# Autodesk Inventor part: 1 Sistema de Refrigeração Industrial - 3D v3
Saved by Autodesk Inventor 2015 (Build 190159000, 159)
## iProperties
Created: 2015-06
Part Number: 1 Sistema de Refrigeração Industrial - 3D v3
Material: Generic
Document SubType Name: Modeling
Designer: Franzi-CAD
Density: 1 g/cm^3
Appearance: 84,84,84_1
Translation Standard: IGES 5.3
FileName: 1 Sistema de RefrigeraÃ§Ã£o Industrial - 3D v3
PreProcessor: AutoCAD 2015 - English
PostProcessor: Build: 160, Release: 2012 RTM - Date: Tue 03/01/2011
Sent Units: millimeter
Uncertainty: 0.01
Author: Franzi-CAD
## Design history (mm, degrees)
node "1 Sistema de Refrigeração Industrial - 3D v3.iges1"
  sketch "3D Sketch1"
sketch "3D Sketch2"
node "1 Sistema de Refrigeração Industrial - 3D v3"
node "1 Sistema de Refrigeração Industrial - 3D v3_1"
node "1 Sistema de Refrigeração Industrial - 3D v3_2"
node "1 Sistema de Refrigeração Industrial - 3D v3_3"
node "1 Sistema de Refrigeração Industrial - 3D v3_4"
node "1 Sistema de Refrigeração Industrial - 3D v3_5"
node "1 Sistema de Refrigeração Industrial - 3D v3_6"
node "1 Sistema de Refrigeração Industrial - 3D v3_7"
node "1 Sistema de Refrigeração Industrial - 3D v3_8"
node "1 Sistema de Refrigeração Industrial - 3D v3_9"
node "1 Sistema de Refrigeração Industrial - 3D v3_10"
node "1 Sistema de Refrigeração Industrial - 3D v3_11"
node "1 Sistema de Refrigeração Industrial - 3D v3_12"
node "1 Sistema de Refrigeração Industrial - 3D v3_13"
node "1 Sistema de Refrigeração Industrial - 3D v3_14"
node "1 Sistema de Refrigeração Industrial - 3D v3_15"
node "1 Sistema de Refrigeração Industrial - 3D v3_16"
node "1 Sistema de Refrigeração Industrial - 3D v3_17"
node "1 Sistema de Refrigeração Industrial - 3D v3_18"
node "1 Sistema de Refrigeração Industrial - 3D v3_19"
node "1 Sistema de Refrigeração Industrial - 3D v3_20"
node "1 Sistema de Refrigeração Industrial - 3D v3_21"
node "1 Sistema de Refrigeração Industrial - 3D v3_22"
node "1 Sistema de Refrigeração Industrial - 3D v3_23"
node "1 Sistema de Refrigeração Industrial - 3D v3_24"
node "1 Sistema de Refrigeração Industrial - 3D v3_25"
node "1 Sistema de Refrigeração Industrial - 3D v3_26"
node "1 Sistema de Refrigeração Industrial - 3D v3_27"
node "1 Sistema de Refrigeração Industrial - 3D v3_28"
node "1 Sistema de Refrigeração Industrial - 3D v3_29"
node "1 Sistema de Refrigeração Industrial - 3D v3_30"
node "1 Sistema de Refrigeração Industrial - 3D v3_31"
node "1 Sistema de Refrigeração Industrial - 3D v3_32"
node "1 Sistema de Refrigeração Industrial - 3D v3_33"
node "1 Sistema de Refrigeração Industrial - 3D v3_34"
node "1 Sistema de Refrigeração Industrial - 3D v3_35"
node "1 Sistema de Refrigeração Industrial - 3D v3_36"
node "1 Sistema de Refrigeração Industrial - 3D v3_37"
node "1 Sistema de Refrigeração Industrial - 3D v3_38"
node "1 Sistema de Refrigeração Industrial - 3D v3_39"
node "1 Sistema de Refrigeração Industrial - 3D v3_40"
node "1 Sistema de Refrigeração Industrial - 3D v3_41"
node "1 Sistema de Refrigeração Industrial - 3D v3_42"
node "1 Sistema de Refrigeração Industrial - 3D v3_43"
node "1 Sistema de Refrigeração Industrial - 3D v3_44"
node "1 Sistema de Refrigeração Industrial - 3D v3_45"
node "1 Sistema de Refrigeração Industrial - 3D v3_46"
node "1 Sistema de Refrigeração Industrial - 3D v3_47"
node "1 Sistema de Refrigeração Industrial - 3D v3_48"
node "1 Sistema de Refrigeração Industrial - 3D v3_49"
node "1 Sistema de Refrigeração Industrial - 3D v3_50"
node "1 Sistema de Refrigeração Industrial - 3D v3_51"
node "1 Sistema de Refrigeração Industrial - 3D v3_52"
node "1 Sistema de Refrigeração Industrial - 3D v3_53"
node "1 Sistema de Refrigeração Industrial - 3D v3_54"
node "1 Sistema de Refrigeração Industrial - 3D v3_55"
node "1 Sistema de Refrigeração Industrial - 3D v3_56"
node "1 Sistema de Refrigeração Industrial - 3D v3_57"
node "1 Sistema de Refrigeração Industrial - 3D v3_58"
node "1 Sistema de Refrigeração Industrial - 3D v3_59"
node "1 Sistema de Refrigeração Industrial - 3D v3_60"
node "1 Sistema de Refrigeração Industrial - 3D v3_61"
node "1 Sistema de Refrigeração Industrial - 3D v3_62"
node "1 Sistema de Refrigeração Industrial - 3D v3_63"
node "1 Sistema de Refrigeração Industrial - 3D v3_64"
node "1 Sistema de Refrigeração Industrial - 3D v3_65"
node "1 Sistema de Refrigeração Industrial - 3D v3_66"
node "1 Sistema de Refrigeração Industrial - 3D v3_67"
node "1 Sistema de Refrigeração Industrial - 3D v3_68"
node "1 Sistema de Refrigeração Industrial - 3D v3_69"
node "1 Sistema de Refrigeração Industrial - 3D v3_70"
node "1 Sistema de Refrigeração Industrial - 3D v3_71"
node "1 Sistema de Refrigeração Industrial - 3D v3_72"
node "1 Sistema de Refrigeração Industrial - 3D v3_73"
node "1 Sistema de Refrigeração Industrial - 3D v3_74"
node "1 Sistema de Refrigeração Industrial - 3D v3_75"
node "1 Sistema de Refrigeração Industrial - 3D v3_76"
node "1 Sistema de Refrigeração Industrial - 3D v3_77"
node "1 Sistema de Refrigeração Industrial - 3D v3_78"
node "1 Sistema de Refrigeração Industrial - 3D v3_79"
node "1 Sistema de Refrigeração Industrial - 3D v3_80"
node "1 Sistema de Refrigeração Industrial - 3D v3_81"
node "1 Sistema de Refrigeração Industrial - 3D v3_82"
node "1 Sistema de Refrigeração Industrial - 3D v3_83"
node "1 Sistema de Refrigeração Industrial - 3D v3_84"
node "1 Sistema de Refrigeração Industrial - 3D v3_85"
node "1 Sistema de Refrigeração Industrial - 3D v3_86"
node "1 Sistema de Refrigeração Industrial - 3D v3_87"
node "1 Sistema de Refrigeração Industrial - 3D v3_88"
node "1 Sistema de Refrigeração Industrial - 3D v3_89"
node "1 Sistema de Refrigeração Industrial - 3D v3_90"
node "1 Sistema de Refrigeração Industrial - 3D v3_91"
node "1 Sistema de Refrigeração Industrial - 3D v3_92"
node "1 Sistema de Refrigeração Industrial - 3D v3_93"
node "1 Sistema de Refrigeração Industrial - 3D v3_94"
node "1 Sistema de Refrigeração Industrial - 3D v3_95"
node "1 Sistema de Refrigeração Industrial - 3D v3_96"
node "1 Sistema de Refrigeração Industrial - 3D v3_97"
node "1 Sistema de Refrigeração Industrial - 3D v3_98"
node "1 Sistema de Refrigeração Industrial - 3D v3_99"
node "1 Sistema de Refrigeração Industrial - 3D v3_100"
node "1 Sistema de Refrigeração Industrial - 3D v3_101"
node "1 Sistema de Refrigeração Industrial - 3D v3_102"
node "1 Sistema de Refrigeração Industrial - 3D v3_103"
node "1 Sistema de Refrigeração Industrial - 3D v3_104"
node "1 Sistema de Refrigeração Industrial - 3D v3_105"
node "1 Sistema de Refrigeração Industrial - 3D v3_106"
node "1 Sistema de Refrigeração Industrial - 3D v3_107"
node "1 Sistema de Refrigeração Industrial - 3D v3_108"
node "1 Sistema de Refrigeração Industrial - 3D v3_109"
node "1 Sistema de Refrigeração Industrial - 3D v3_110"
node "1 Sistema de Refrigeração Industrial - 3D v3_111"
node "1 Sistema de Refrigeração Industrial - 3D v3_112"
node "1 Sistema de Refrigeração Industrial - 3D v3_113"
node "1 Sistema de Refrigeração Industrial - 3D v3_114"
node "1 Sistema de Refrigeração Industrial - 3D v3_115"
node "1 Sistema de Refrigeração Industrial - 3D v3_116"
node "1 Sistema de Refrigeração Industrial - 3D v3_117"
node "1 Sistema de Refrigeração Industrial - 3D v3_118"
node "1 Sistema de Refrigeração Industrial - 3D v3_119"
node "1 Sistema de Refrigeração Industrial - 3D v3_120"
node "1 Sistema de Refrigeração Industrial - 3D v3_121"
node "1 Sistema de Refrigeração Industrial - 3D v3_122"
node "1 Sistema de Refrigeração Industrial - 3D v3_123"
node "1 Sistema de Refrigeração Industrial - 3D v3_124"
node "1 Sistema de Refrigeração Industrial - 3D v3_125"
node "1 Sistema de Refrigeração Industrial - 3D v3_126"
node "1 Sistema de Refrigeração Industrial - 3D v3_127"
node "1 Sistema de Refrigeração Industrial - 3D v3_128"
node "1 Sistema de Refrigeração Industrial - 3D v3_129"
node "1 Sistema de Refrigeração Industrial - 3D v3_130"
node "1 Sistema de Refrigeração Industrial - 3D v3_131"
node "1 Sistema de Refrigeração Industrial - 3D v3_132"
node "1 Sistema de Refrigeração Industrial - 3D v3_133"
node "1 Sistema de Refrigeração Industrial - 3D v3_134"
node "1 Sistema de Refrigeração Industrial - 3D v3_135"
node "1 Sistema de Refrigeração Industrial - 3D v3_136"
node "1 Sistema de Refrigeração Industrial - 3D v3_137"
node "1 Sistema de Refrigeração Industrial - 3D v3_138"
node "1 Sistema de Refrigeração Industrial - 3D v3_139"
node "1 Sistema de Refrigeração Industrial - 3D v3_140"
node "1 Sistema de Refrigeração Industrial - 3D v3_141"
node "1 Sistema de Refrigeração Industrial - 3D v3_142"
node "1 Sistema de Refrigeração Industrial - 3D v3_143"
node "1 Sistema de Refrigeração Industrial - 3D v3_144"
node "1 Sistema de Refrigeração Industrial - 3D v3_145"
node "1 Sistema de Refrigeração Industrial - 3D v3_146"
node "1 Sistema de Refrigeração Industrial - 3D v3_147"
node "1 Sistema de Refrigeração Industrial - 3D v3_148"
node "1 Sistema de Refrigeração Industrial - 3D v3_149"
node "1 Sistema de Refrigeração Industrial - 3D v3_150"
node "1 Sistema de Refrigeração Industrial - 3D v3_151"
node "1 Sistema de Refrigeração Industrial - 3D v3_152"
node "1 Sistema de Refrigeração Industrial - 3D v3_153"
node "1 Sistema de Refrigeração Industrial - 3D v3_154"
node "1 Sistema de Refrigeração Industrial - 3D v3_155"
node "1 Sistema de Refrigeração Industrial - 3D v3_156"
node "1 Sistema de Refrigeração Industrial - 3D v3_157"
node "1 Sistema de Refrigeração Industrial - 3D v3_158"
node "1 Sistema de Refrigeração Industrial - 3D v3_159"
node "1 Sistema de Refrigeração Industrial - 3D v3_160"
node "1 Sistema de Refrigeração Industrial - 3D v3_161"
node "1 Sistema de Refrigeração Industrial - 3D v3_162"
node "1 Sistema de Refrigeração Industrial - 3D v3_163"
node "1 Sistema de Refrigeração Industrial - 3D v3_164"
node "1 Sistema de Refrigeração Industrial - 3D v3_165"
node "1 Sistema de Refrigeração Industrial - 3D v3_166"
node "1 Sistema de Refrigeração Industrial - 3D v3_167"
node "1 Sistema de Refrigeração Industrial - 3D v3_168"
node "1 Sistema de Refrigeração Industrial - 3D v3_169"
node "1 Sistema de Refrigeração Industrial - 3D v3_170"
node "1 Sistema de Refrigeração Industrial - 3D v3_171"
node "1 Sistema de Refrigeração Industrial - 3D v3_172"
node "1 Sistema de Refrigeração Industrial - 3D v3_173"
node "1 Sistema de Refrigeração Industrial - 3D v3_174"
node "1 Sistema de Refrigeração Industrial - 3D v3_175"
node "1 Sistema de Refrigeração Industrial - 3D v3_176"
node "1 Sistema de Refrigeração Industrial - 3D v3_177"
node "1 Sistema de Refrigeração Industrial - 3D v3_178"
node "1 Sistema de Refrigeração Industrial - 3D v3_179"
node "1 Sistema de Refrigeração Industrial - 3D v3_180"
node "1 Sistema de Refrigeração Industrial - 3D v3_181"
node "1 Sistema de Refrigeração Industrial - 3D v3_182"
node "1 Sistema de Refrigeração Industrial - 3D v3_183"
node "1 Sistema de Refrigeração Industrial - 3D v3_184"
node "1 Sistema de Refrigeração Industrial - 3D v3_185"
node "1 Sistema de Refrigeração Industrial - 3D v3_186"
node "1 Sistema de Refrigeração Industrial - 3D v3_187"
node "1 Sistema de Refrigeração Industrial - 3D v3_188"
node "1 Sistema de Refrigeração Industrial - 3D v3_189"
node "1 Sistema de Refrigeração Industrial - 3D v3_190"
node "1 Sistema de Refrigeração Industrial - 3D v3_191"
node "1 Sistema de Refrigeração Industrial - 3D v3_192"
node "1 Sistema de Refrigeração Industrial - 3D v3_193"
node "1 Sistema de Refrigeração Industrial - 3D v3_194"
node "1 Sistema de Refrigeração Industrial - 3D v3_195"
node "1 Sistema de Refrigeração Industrial - 3D v3_196"
node "1 Sistema de Refrigeração Industrial - 3D v3_197"
node "1 Sistema de Refrigeração Industrial - 3D v3_198"
node "1 Sistema de Refrigeração Industrial - 3D v3_199"
node "1 Sistema de Refrigeração Industrial - 3D v3_200"
node "1 Sistema de Refrigeração Industrial - 3D v3_201"
node "1 Sistema de Refrigeração Industrial - 3D v3_202"
node "1 Sistema de Refrigeração Industrial - 3D v3_203"
node "1 Sistema de Refrigeração Industrial - 3D v3_204"
node "1 Sistema de Refrigeração Industrial - 3D v3_205"
node "1 Sistema de Refrigeração Industrial - 3D v3_206"
node "1 Sistema de Refrigeração Industrial - 3D v3_207"
node "1 Sistema de Refrigeração Industrial - 3D v3_208"
node "1 Sistema de Refrigeração Industrial - 3D v3_209"
node "1 Sistema de Refrigeração Industrial - 3D v3_210"
node "1 Sistema de Refrigeração Industrial - 3D v3_211"
node "1 Sistema de Refrigeração Industrial - 3D v3_212"
node "1 Sistema de Refrigeração Industrial - 3D v3_213"
node "1 Sistema de Refrigeração Industrial - 3D v3_214"
node "1 Sistema de Refrigeração Industrial - 3D v3_215"
node "1 Sistema de Refrigeração Industrial - 3D v3_216"
node "1 Sistema de Refrigeração Industrial - 3D v3_217"
node "1 Sistema de Refrigeração Industrial - 3D v3_218"
node "1 Sistema de Refrigeração Industrial - 3D v3_219"
node "1 Sistema de Refrigeração Industrial - 3D v3_220"
node "1 Sistema de Refrigeração Industrial - 3D v3_221"
node "1 Sistema de Refrigeração Industrial - 3D v3_222"
node "1 Sistema de Refrigeração Industrial - 3D v3_223"
node "1 Sistema de Refrigeração Industrial - 3D v3_224"
node "1 Sistema de Refrigeração Industrial - 3D v3_225"
node "1 Sistema de Refrigeração Industrial - 3D v3_226"
node "1 Sistema de Refrigeração Industrial - 3D v3_227"
node "1 Sistema de Refrigeração Industrial - 3D v3_228"
node "1 Sistema de Refrigeração Industrial - 3D v3_229"
node "1 Sistema de Refrigeração Industrial - 3D v3_230"
node "1 Sistema de Refrigeração Industrial - 3D v3_231"
node "1 Sistema de Refrigeração Industrial - 3D v3_232"
node "1 Sistema de Refrigeração Industrial - 3D v3_233"
node "1 Sistema de Refrigeração Industrial - 3D v3_234"
node "1 Sistema de Refrigeração Industrial - 3D v3_235"
node "1 Sistema de Refrigeração Industrial - 3D v3_236"
node "1 Sistema de Refrigeração Industrial - 3D v3_237"
node "1 Sistema de Refrigeração Industrial - 3D v3_238"
node "1 Sistema de Refrigeração Industrial - 3D v3_239"
node "1 Sistema de Refrigeração Industrial - 3D v3_240"
node "1 Sistema de Refrigeração Industrial - 3D v3_241"
node "1 Sistema de Refrigeração Industrial - 3D v3_242"
node "1 Sistema de Refrigeração Industrial - 3D v3_243"
node "1 Sistema de Refrigeração Industrial - 3D v3_244"
node "1 Sistema de Refrigeração Industrial - 3D v3_245"
node "1 Sistema de Refrigeração Industrial - 3D v3_246"
node "1 Sistema de Refrigeração Industrial - 3D v3_247"
node "1 Sistema de Refrigeração Industrial - 3D v3_248"
node "1 Sistema de Refrigeração Industrial - 3D v3_249"
node "1 Sistema de Refrigeração Industrial - 3D v3_250"
node "1 Sistema de Refrigeração Industrial - 3D v3_251"
node "1 Sistema de Refrigeração Industrial - 3D v3_252"
node "1 Sistema de Refrigeração Industrial - 3D v3_253"
node "1 Sistema de Refrigeração Industrial - 3D v3_254"
node "1 Sistema de Refrigeração Industrial - 3D v3_255"
node "1 Sistema de Refrigeração Industrial - 3D v3_256"
node "1 Sistema de Refrigeração Industrial - 3D v3_257"
node "1 Sistema de Refrigeração Industrial - 3D v3_258"
node "1 Sistema de Refrigeração Industrial - 3D v3_259"
node "1 Sistema de Refrigeração Industrial - 3D v3_260"
node "1 Sistema de Refrigeração Industrial - 3D v3_261"
node "1 Sistema de Refrigeração Industrial - 3D v3_262"
node "1 Sistema de Refrigeração Industrial - 3D v3_263"
node "1 Sistema de Refrigeração Industrial - 3D v3_264"
node "1 Sistema de Refrigeração Industrial - 3D v3_265"
node "1 Sistema de Refrigeração Industrial - 3D v3_266"
node "1 Sistema de Refrigeração Industrial - 3D v3_267"
node "1 Sistema de Refrigeração Industrial - 3D v3_268"
node "1 Sistema de Refrigeração Industrial - 3D v3_269"
node "1 Sistema de Refrigeração Industrial - 3D v3_270"
node "1 Sistema de Refrigeração Industrial - 3D v3_271"
node "1 Sistema de Refrigeração Industrial - 3D v3_272"
node "1 Sistema de Refrigeração Industrial - 3D v3_273"
node "1 Sistema de Refrigeração Industrial - 3D v3_274"
node "1 Sistema de Refrigeração Industrial - 3D v3_275"
node "1 Sistema de Refrigeração Industrial - 3D v3_276"
node "1 Sistema de Refrigeração Industrial - 3D v3_277"
node "1 Sistema de Refrigeração Industrial - 3D v3_278"
node "1 Sistema de Refrigeração Industrial - 3D v3_279"
node "1 Sistema de Refrigeração Industrial - 3D v3_280"
node "1 Sistema de Refrigeração Industrial - 3D v3_281"
node "1 Sistema de Refrigeração Industrial - 3D v3_282"
node "1 Sistema de Refrigeração Industrial - 3D v3_283"
node "1 Sistema de Refrigeração Industrial - 3D v3_284"
node "1 Sistema de Refrigeração Industrial - 3D v3_285"
node "1 Sistema de Refrigeração Industrial - 3D v3_286"
node "1 Sistema de Refrigeração Industrial - 3D v3_287"
node "1 Sistema de Refrigeração Industrial - 3D v3_288"
node "1 Sistema de Refrigeração Industrial - 3D v3_289"
node "1 Sistema de Refrigeração Industrial - 3D v3_290"
node "1 Sistema de Refrigeração Industrial - 3D v3_291"
node "1 Sistema de Refrigeração Industrial - 3D v3_292"
node "1 Sistema de Refrigeração Industrial - 3D v3_293"
node "1 Sistema de Refrigeração Industrial - 3D v3_294"
node "1 Sistema de Refrigeração Industrial - 3D v3_295"
node "1 Sistema de Refrigeração Industrial - 3D v3_296"
node "1 Sistema de Refrigeração Industrial - 3D v3_297"
node "1 Sistema de Refrigeração Industrial - 3D v3_298"
node "1 Sistema de Refrigeração Industrial - 3D v3_299"
node "1 Sistema de Refrigeração Industrial - 3D v3_300"
node "1 Sistema de Refrigeração Industrial - 3D v3_301"
node "1 Sistema de Refrigeração Industrial - 3D v3_302"
node "1 Sistema de Refrigeração Industrial - 3D v3_303"
node "1 Sistema de Refrigeração Industrial - 3D v3_304"
node "1 Sistema de Refrigeração Industrial - 3D v3_305"
node "1 Sistema de Refrigeração Industrial - 3D v3_306"
node "1 Sistema de Refrigeração Industrial - 3D v3_307"
node "1 Sistema de Refrigeração Industrial - 3D v3_308"
node "1 Sistema de Refrigeração Industrial - 3D v3_309"
node "1 Sistema de Refrigeração Industrial - 3D v3_310"
node "1 Sistema de Refrigeração Industrial - 3D v3_311"
node "1 Sistema de Refrigeração Industrial - 3D v3_312"
node "1 Sistema de Refrigeração Industrial - 3D v3_313"
node "1 Sistema de Refrigeração Industrial - 3D v3_314"
node "1 Sistema de Refrigeração Industrial - 3D v3_315"
node "1 Sistema de Refrigeração Industrial - 3D v3_316"
node "1 Sistema de Refrigeração Industrial - 3D v3_317"
node "1 Sistema de Refrigeração Industrial - 3D v3_318"
node "1 Sistema de Refrigeração Industrial - 3D v3_319"
node "1 Sistema de Refrigeração Industrial - 3D v3_320"
node "1 Sistema de Refrigeração Industrial - 3D v3_321"
node "1 Sistema de Refrigeração Industrial - 3D v3_322"
node "1 Sistema de Refrigeração Industrial - 3D v3_323"
node "1 Sistema de Refrigeração Industrial - 3D v3_324"
node "1 Sistema de Refrigeração Industrial - 3D v3_325"
node "1 Sistema de Refrigeração Industrial - 3D v3_326"
node "1 Sistema de Refrigeração Industrial - 3D v3_327"
node "1 Sistema de Refrigeração Industrial - 3D v3_328"
node "1 Sistema de Refrigeração Industrial - 3D v3_329"
node "1 Sistema de Refrigeração Industrial - 3D v3_330"
node "1 Sistema de Refrigeração Industrial - 3D v3_331"
node "1 Sistema de Refrigeração Industrial - 3D v3_332"
node "1 Sistema de Refrigeração Industrial - 3D v3_333"
node "1 Sistema de Refrigeração Industrial - 3D v3_334"
node "1 Sistema de Refrigeração Industrial - 3D v3_335"
node "1 Sistema de Refrigeração Industrial - 3D v3_336"
node "1 Sistema de Refrigeração Industrial - 3D v3_337"
node "Base1"
node "Base2"
node "Base3"
node "Base4"
node "Base5"
node "Base6"
node "Base7"
node "Base8"
node "Base9"
node "Base10"
node "Base11"
node "Base12"
node "Base13"
node "Base14"
node "Base15"
node "Base16"
node "Base17"
node "Base18"
node "Base19"
node "Base20"
node "Base21"
node "Base22"
node "Base23"
node "Base24"
node "Base25"
node "Base26"
node "Base27"
node "Base28"
node "Base29"
node "Base30"
node "Base31"
node "Base32"
node "Base33"
node "Base34"
node "Base35"
node "Base36"
node "Base37"
node "Base38"
node "Base39"
node "Base40"
node "Base41"
node "Base42"
node "Base43"
node "Base44"
node "Base45"
node "Base46"
node "Base47"
node "Base48"
node "Base49"
node "Base50"
node "Base51"
node "Base52"
node "Base53"
node "Base54"
node "Base55"
node "Base56"
node "Base57"
node "Base58"
node "Base59"
node "Base60"
node "Base61"
node "Base62"
node "Base63"
node "Base64"
node "Base65"
node "Base66"
node "Base67"
node "Base68"
node "Base69"
node "Base70"
node "Base71"
node "Base72"
node "Base73"
node "Base74"
node "Base75"
node "Base76"
node "Base77"
node "Base78"
node "Base79"
node "Base80"
node "Base81"
node "Base82"
node "Base83"
node "Base84"
node "Base85"
node "Base86"
node "Base87"
node "Base88"
node "Base89"
node "Base90"
node "Base91"
node "Base92"
node "Base93"
node "Base94"
node "Base95"
node "Base96"
node "Base97"
node "Base98"
node "Base99"
node "Base100"
node "Base101"
node "Base102"
node "Base103"
node "Base104"
node "Base105"
node "Base106"
node "Base107"
node "Base108"
node "Base109"
node "Base110"
node "Base111"
node "Base112"
node "Base113"
node "Base114"
node "Base115"
node "Base116"
node "Base117"
node "Base118"
node "Base119"
node "Base120"
node "Base121"
node "Base122"
node "Base123"
node "Base124"
node "Base125"
node "Base126"
node "Base127"
node "Base128"
node "Base129"
node "Base130"
node "Base131"
node "Base132"
node "Base133"
node "Base134"
node "Base135"
node "Base136"
node "Base137"
node "Base138"
node "Base139"
node "Base140"
node "Base141"
node "Base142"
node "Base143"
node "Base144"
node "Base145"
node "Base146"
node "Base147"
node "Base148"
node "Base149"
node "Base150"
node "Base151"
node "Base152"
node "Base153"
node "Base154"
node "Base155"
node "Base156"
node "Base157"
node "Base158"
node "Base159"
node "Base160"
node "Base161"
node "Base162"
node "Base163"
node "Base164"
node "Base165"
node "Base166"
node "Base167"
node "Base168"
node "Base169"
node "Base170"
node "Base171"
node "Base172"
node "Base173"
node "Base174"
node "Base175"
node "Base176"
node "Base177"
node "Base178"
node "Base179"
node "Base180"
node "Base181"
node "Base182"
node "Base183"
node "Base184"
node "Base185"
node "Base186"
node "Base187"
node "Base188"
node "Base189"
node "Base190"
node "Base191"
node "Base192"
node "Base193"
node "Base194"
node "Base195"
node "Base196"
node "Base197"
node "Base198"
node "Base199"
node "Base200"
node "Base201"
node "Base202"
node "Base203"
node "Base204"
node "Base205"
node "Base206"
node "Base207"
node "Base208"
node "Base209"
node "Base210"
node "Base211"
node "Base212"
node "Base213"
node "Base214"
node "Base215"
node "Base216"
node "Base217"
node "Base218"
node "Base219"
node "Base220"
node "Base221"
node "Base222"
node "Base223"
node "Base224"
node "Base225"
node "Base226"
node "Base227"
node "Base228"
node "Base229"
node "Base230"
node "Base231"
node "Base232"
node "Base233"
node "Base234"
node "Base235"
node "Base236"
node "Base237"
node "Base238"
node "Base239"
node "Base240"
node "Base241"
node "Base242"
node "Base243"
node "Base244"
node "Base245"
node "Base246"
node "Base247"
node "Base248"
node "Base249"
node "Base250"
node "Base251"
node "Base252"
node "Base253"
node "Base254"
node "Base255"
node "Base256"
node "Base257"
node "Base258"
node "Base259"
node "Base260"
node "Base261"
node "Base262"
node "Base263"
node "Base264"
node "Base265"
node "Base266"
node "Base267"
node "Base268"
node "Base269"
node "Base270"
node "Base271"
node "Base272"
node "Base273"
node "Base274"
node "Base275"
node "Base276"
node "Base277"
node "Base278"
node "Base279"
node "Base280"
node "Base281"
node "Base282"
node "Base283"
node "Base284"
node "Base285"
node "Base286"
node "Base287"
node "Base288"
node "Base289"
node "Base290"
node "Base291"
node "Base292"
node "Base293"
node "Base294"
node "Base295"
node "Base296"
node "Base297"
node "Base298"
node "Base299"
node "Base300"
node "Base301"
node "Base302"
node "Base303"
node "Base304"
node "Base305"
node "Base306"
node "Base307"
node "Base308"
node "Base309"
node "Base310"
node "Base311"
node "Base312"
node "Base313"
node "Base314"
node "Base315"
node "Base316"
node "Base317"
node "Base318"
node "Base319"
node "Base320"
node "Base321"
node "Base322"
node "Base323"
node "Base324"
node "Base325"
node "Base326"
node "Base327"
node "Base328"
node "Base329"
node "Base330"
node "Base331"
node "Base332"
node "Base333"
node "Base334"
node "Base335"
node "Base336"
node "Base337"
node "Base338"
feature "Composite1"
body "Srf1"
